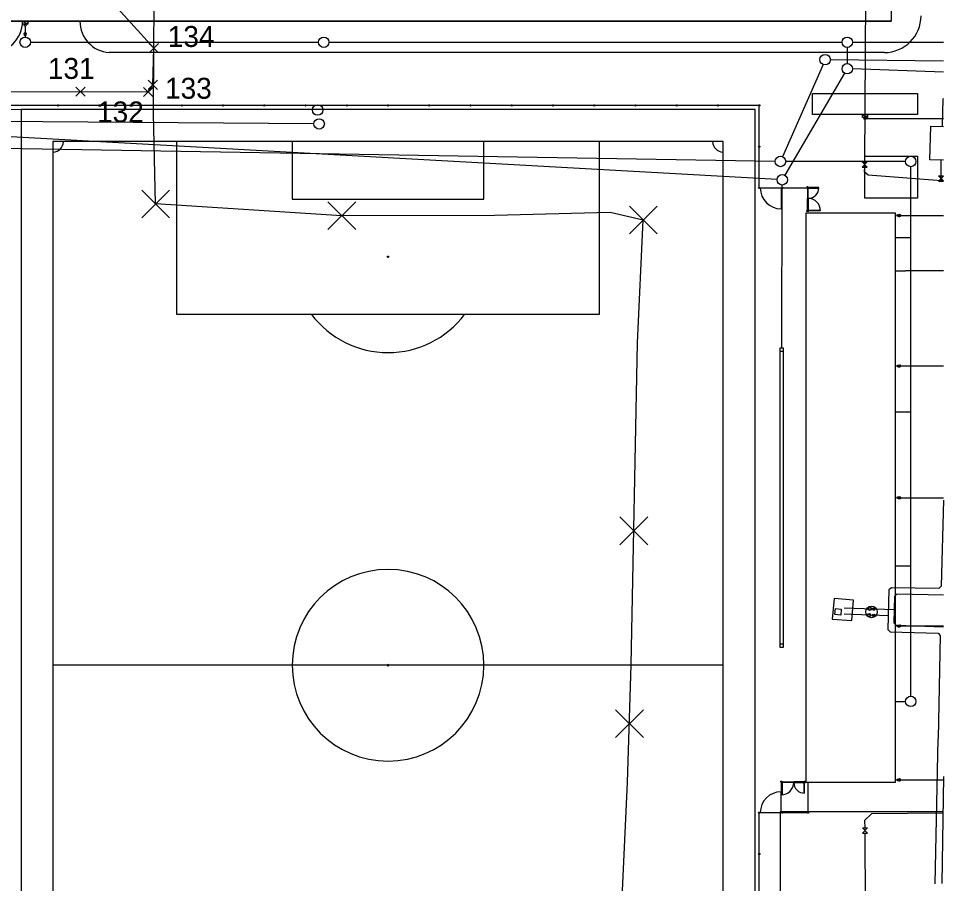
# Model space of a CAD drawing. Extents: x -264205 to -263744, y -1242450 to -1242050.
# Drawn here: x -264042.8 to -263954.5, y -1242261.8 to -1242179.2 of the extents above; entities that cross this region are included whole.
import ezdxf

# ---------------------------------------------------------------- set-up
doc = ezdxf.new("R2010")
doc.units = 0
for name, color, linetype in [('KFA_63-1_TELEKOM_PRELOZKA', 7, 'Continuous'), ('KFA_BODY_CISLO', 7, 'Continuous'), ('KFA_BODY_SYMBOL', 7, 'Continuous'), ('KFA_JESTV_IS_DSP', 7, 'Continuous'), ('KFA_SITUACIA_DSP', 7, 'Continuous'), ('KFA_TELEKOM_POVODNA_TRASA', 7, 'Continuous'), ('POPIS', 7, 'Continuous')]:
    doc.layers.add(name, color=color, linetype=linetype)

msp = doc.modelspace()

# ---------------------------------------------------------------- linework, layer by layer
at = {"layer": 'KFA_63-1_TELEKOM_PRELOZKA'}
msp.add_lwpolyline([(-264119.225, -1242186.724), (-264097.679, -1242186.215), (-264066.654, -1242186.22), (-264036.882, -1242186.217), (-264030.42, -1242186.248), (-264029.972, -1242185.571), (-264029.872, -1242182.075)], dxfattribs=at)
at = {"layer": 'KFA_BODY_SYMBOL'}
for p, q in [((-264030.314, -1242182.517), (-264029.43, -1242181.633)), ((-264029.43, -1242182.517), (-264030.314, -1242181.633)), ((-264029.872, -1242182.075), (-264029.872, -1242182.075)), ((-264037.324, -1242186.659), (-264036.44, -1242185.775)), ((-264036.44, -1242186.659), (-264037.324, -1242185.775)), ((-264030.862, -1242186.69), (-264029.978, -1242185.806)), ((-264029.978, -1242186.69), (-264030.862, -1242185.806)), ((-264030.414, -1242186.013), (-264029.53, -1242185.129)), ((-264029.53, -1242186.013), (-264030.414, -1242185.129)), ((-264029.972, -1242185.571), (-264029.972, -1242185.571)), ((-264036.882, -1242186.217), (-264036.882, -1242186.217)), ((-264030.42, -1242186.248), (-264030.42, -1242186.248))]:
    msp.add_line(p, q, dxfattribs=at)
at = {"layer": 'KFA_JESTV_IS_DSP'}
for p, q in [((-263961.582, -1242115.554), (-263961.999, -1242192.922)), ((-263954.47, -1242183.294), (-263965.273, -1242183.165)), ((-263965.974, -1242183.616), (-263969.841, -1242192.426)), ((-263954.47, -1242184.349), (-263963.161, -1242184.046)), ((-263963.914, -1242184.46), (-263969.615, -1242194.201)), ((-263954.509, -1242186.913), (-263954.47, -1242186.884)), ((-263954.57, -1242189.535), (-263954.509, -1242186.913)), ((-264014.599, -1242189.295), (-264103.868, -1242188.645)), ((-264014.738, -1242187.967), (-264101.789, -1242187.812)), ((-263955.775, -1242192.739), (-263955.679, -1242189.503)), ((-263955.679, -1242189.503), (-263954.47, -1242189.537)), ((-263970.367, -1242194.605), (-264044.102, -1242190.483)), ((-263970.542, -1242192.875), (-264044.328, -1242191.641)), ((-263962.251, -1242192.922), (-263961.751, -1242192.922)), ((-263961.751, -1242192.922), (-263962.251, -1242193.422)), ((-263961.751, -1242193.422), (-263962.251, -1242192.922)), ((-263954.47, -1242192.759), (-263955.775, -1242192.739)), ((-263954.693, -1242194.518), (-263954.696, -1242192.756)), ((-263962.251, -1242193.422), (-263961.751, -1242193.422)), ((-263962.017, -1242193.422), (-263962.046, -1242193.838)), ((-263962.046, -1242193.838), (-263961.65, -1242194.164)), ((-263961.65, -1242194.164), (-263954.663, -1242194.7)), ((-263954.943, -1242194.268), (-263954.47, -1242194.268)), ((-263954.47, -1242194.741), (-263954.943, -1242194.268)), ((-263954.47, -1242194.295), (-263954.943, -1242194.768)), ((-263954.943, -1242194.768), (-263954.47, -1242194.768)), ((-263954.663, -1242194.7), (-263954.693, -1242194.518)), ((-263954.663, -1242194.7), (-263954.47, -1242194.703)), ((-263954.47, -1242225.226), (-263954.692, -1242233.447)), ((-263959.451, -1242233.59), (-263959.696, -1242233.784)), ((-263954.912, -1242233.658), (-263959.451, -1242233.59)), ((-263954.692, -1242233.447), (-263954.912, -1242233.658)), ((-263959.696, -1242233.784), (-263959.771, -1242237.559)), ((-263959.189, -1242236.963), (-263959.11, -1242234.394)), ((-263959.11, -1242234.394), (-263958.895, -1242234.164)), ((-263958.895, -1242234.164), (-263954.47, -1242234.271)), ((-263964.927, -1242234.61), (-263965.088, -1242236.571)), ((-263963.078, -1242234.762), (-263964.927, -1242234.61)), ((-263963.239, -1242236.723), (-263963.078, -1242234.762)), ((-263964.833, -1242236.15), (-263964.786, -1242235.573)), ((-263964.285, -1242236.195), (-263964.833, -1242236.15)), ((-263964.786, -1242235.573), (-263964.238, -1242235.618)), ((-263964.238, -1242235.618), (-263964.285, -1242236.195)), ((-263959.149, -1242235.676), (-263963.972, -1242235.519)), ((-263959.745, -1242236.267), (-263963.952, -1242236.1)), ((-263965.088, -1242236.571), (-263963.239, -1242236.723)), ((-263958.966, -1242237.191), (-263959.189, -1242236.963)), ((-263954.47, -1242237.349), (-263958.966, -1242237.191)), ((-263959.771, -1242237.559), (-263959.557, -1242237.791)), ((-263959.557, -1242237.791), (-263954.983, -1242237.917)), ((-263954.983, -1242237.917), (-263954.788, -1242238.153)), ((-263954.788, -1242238.153), (-263954.978, -1242247.991)), ((-263955.264, -1242261.849), (-263954.978, -1242247.991)), ((-263954.47, -1242251.609), (-263954.644, -1242261.82)), ((-263961.355, -1242255.168), (-263962.028, -1242255.805)), ((-263954.47, -1242255.107), (-263961.355, -1242255.168)), ((-263962.221, -1242256.501), (-263961.721, -1242256.501)), ((-263961.721, -1242256.501), (-263962.221, -1242257.001)), ((-263961.721, -1242257.001), (-263962.221, -1242256.501)), ((-263962.028, -1242255.805), (-263961.971, -1242256.501)), ((-263962.221, -1242257.001), (-263961.721, -1242257.001)), ((-263961.971, -1242257.001), (-263961.846, -1242321.299))]:
    msp.add_line(p, q, dxfattribs=at)
for centre, radius in [((-263965.773, -1242183.159), 0.5), ((-263963.661, -1242184.028), 0.5), ((-264014.238, -1242187.968), 0.5), ((-264014.099, -1242189.299), 0.5), ((-263970.042, -1242192.883), 0.5), ((-263969.868, -1242194.633), 0.5), ((-263961.345, -1242235.895), 0.556), ((-263961.522, -1242235.583), 0.164), ((-263961.583, -1242236.191), 0.164), ((-263961.138, -1242235.62), 0.122), ((-263961.128, -1242236.214), 0.122)]:
    msp.add_circle(centre, radius, dxfattribs=at)
at = {"layer": 'KFA_SITUACIA_DSP'}
for p, q in [((-263959.468, -1242059.534), (-263959.468, -1242179.482)), ((-264131.568, -1242179.482), (-263959.468, -1242179.482)), ((-263959.468, -1242179.482), (-264131.568, -1242179.482)), ((-263959.468, -1242179.482), (-264077.23, -1242179.482)), ((-264042.417, -1242179.482), (-264041.917, -1242179.482)), ((-264042.417, -1242179.772), (-264042.417, -1242179.482)), ((-264042.417, -1242179.482), (-264041.917, -1242179.772)), ((-264042.417, -1242179.482), (-264041.917, -1242179.772)), ((-264041.917, -1242179.482), (-264042.417, -1242179.482)), ((-264041.917, -1242179.772), (-264042.417, -1242179.772)), ((-264041.917, -1242179.482), (-264041.917, -1242179.772)), ((-264041.917, -1242179.772), (-264041.917, -1242179.482)), ((-264042.167, -1242179.972), (-264042.167, -1242181)), ((-264041.667, -1242181.5), (-264014.161, -1242181.5)), ((-264013.161, -1242181.5), (-263964.161, -1242181.5)), ((-263963.161, -1242181.5), (-263954.47, -1242181.5)), ((-263963.661, -1242182), (-263963.661, -1242183.528)), ((-263960.118, -1242182.482), (-264034.158, -1242182.482)), ((-263972.068, -1242187.532), (-264118.068, -1242187.532)), ((-264039.089, -1242187.532), (-264038.969, -1242187.532)), ((-264039.029, -1242187.592), (-264039.029, -1242187.472)), ((-264035.15, -1242187.532), (-264035.03, -1242187.532)), ((-264035.09, -1242187.592), (-264035.09, -1242187.472)), ((-264031.211, -1242187.532), (-264031.091, -1242187.532)), ((-264031.151, -1242187.592), (-264031.151, -1242187.472)), ((-264027.272, -1242187.532), (-264027.152, -1242187.532)), ((-264027.212, -1242187.592), (-264027.212, -1242187.472)), ((-264023.333, -1242187.532), (-264023.213, -1242187.532)), ((-264023.273, -1242187.592), (-264023.273, -1242187.472)), ((-264019.394, -1242187.532), (-264019.274, -1242187.532)), ((-264019.334, -1242187.592), (-264019.334, -1242187.472)), ((-264015.456, -1242187.532), (-264015.336, -1242187.532)), ((-264015.396, -1242187.592), (-264015.396, -1242187.472)), ((-264011.517, -1242187.532), (-264011.397, -1242187.532)), ((-264011.457, -1242187.592), (-264011.457, -1242187.472)), ((-264007.578, -1242187.532), (-264007.458, -1242187.532)), ((-264007.518, -1242187.592), (-264007.518, -1242187.472)), ((-264003.639, -1242187.532), (-264003.519, -1242187.532)), ((-264003.579, -1242187.592), (-264003.579, -1242187.472)), ((-263999.7, -1242187.532), (-263999.58, -1242187.532)), ((-263999.64, -1242187.592), (-263999.64, -1242187.472)), ((-263995.761, -1242187.532), (-263995.641, -1242187.532)), ((-263995.701, -1242187.592), (-263995.701, -1242187.472)), ((-263991.822, -1242187.532), (-263991.702, -1242187.532)), ((-263991.762, -1242187.592), (-263991.762, -1242187.472)), ((-263987.883, -1242187.532), (-263987.763, -1242187.532)), ((-263987.823, -1242187.592), (-263987.823, -1242187.472)), ((-263983.944, -1242187.532), (-263983.824, -1242187.532)), ((-263983.884, -1242187.592), (-263983.884, -1242187.472)), ((-263980.006, -1242187.532), (-263979.886, -1242187.532)), ((-263979.946, -1242187.592), (-263979.946, -1242187.472)), ((-263976.067, -1242187.532), (-263975.947, -1242187.532)), ((-263976.007, -1242187.592), (-263976.007, -1242187.472)), ((-263972.128, -1242187.532), (-263972.008, -1242187.532)), ((-263972.068, -1242187.592), (-263972.068, -1242187.472)), ((-263972.068, -1242195.407), (-263972.068, -1242187.532)), ((-263962.218, -1242188.382), (-263961.718, -1242188.382)), ((-263962.218, -1242188.672), (-263962.218, -1242188.382)), ((-263962.218, -1242188.382), (-263961.718, -1242188.672)), ((-263962.218, -1242188.382), (-263961.718, -1242188.672)), ((-263961.718, -1242188.382), (-263962.218, -1242188.382)), ((-263961.718, -1242188.382), (-263961.718, -1242188.672)), ((-263961.718, -1242188.672), (-263961.718, -1242188.382)), ((-263961.718, -1242188.672), (-263962.218, -1242188.672)), ((-263961.868, -1242188.772), (-263954.47, -1242188.772)), ((-263975.518, -1242190.982), (-264039.518, -1242190.982)), ((-264039.518, -1242190.982), (-264039.518, -1242290.982)), ((-264027.678, -1242207.482), (-264027.678, -1242190.982)), ((-264016.678, -1242190.982), (-264016.678, -1242196.482)), ((-263998.358, -1242196.482), (-263998.358, -1242190.982)), ((-263987.358, -1242190.982), (-263987.358, -1242207.482)), ((-263975.518, -1242290.982), (-263975.518, -1242190.982)), ((-263972.128, -1242191.47), (-263972.008, -1242191.47)), ((-263972.068, -1242191.41), (-263972.068, -1242191.53)), ((-263958.097, -1242192.883), (-263969.542, -1242192.883)), ((-263957.597, -1242243.932), (-263957.597, -1242193.383)), ((-263972.068, -1242195.407), (-263967.418, -1242195.407)), ((-263969.968, -1242195.407), (-263969.968, -1242197.407)), ((-263969.921, -1242210.683), (-263969.869, -1242195.133)), ((-263967.413, -1242195.307), (-263967.513, -1242195.307)), ((-263967.513, -1242195.307), (-263967.513, -1242195.407)), ((-263967.513, -1242195.407), (-263967.413, -1242195.407)), ((-263967.425, -1242195.32), (-263967.5, -1242195.32)), ((-263967.5, -1242195.32), (-263967.5, -1242195.395)), ((-263967.5, -1242195.395), (-263967.425, -1242195.395)), ((-263967.463, -1242195.407), (-263967.463, -1242196.395)), ((-263967.388, -1242195.407), (-263967.463, -1242195.407)), ((-263967.425, -1242195.395), (-263967.425, -1242195.32)), ((-263967.425, -1242195.395), (-263967.425, -1242195.345)), ((-263967.425, -1242195.345), (-263967.325, -1242195.345)), ((-263967.413, -1242195.407), (-263967.413, -1242195.307)), ((-263967.413, -1242195.357), (-263967.363, -1242195.357)), ((-263967.388, -1242196.395), (-263967.388, -1242195.407)), ((-263967.363, -1242195.457), (-263967.388, -1242195.457)), ((-263966.388, -1242195.371), (-263967.375, -1242195.37)), ((-263967.375, -1242195.37), (-263967.375, -1242195.445)), ((-263967.375, -1242195.445), (-263966.388, -1242195.446)), ((-263967.363, -1242195.357), (-263967.363, -1242195.457)), ((-263967.325, -1242195.345), (-263967.325, -1242195.37)), ((-264016.678, -1242196.482), (-263998.358, -1242196.482)), ((-263967.463, -1242197.557), (-263967.463, -1242196.42)), ((-263967.388, -1242196.42), (-263967.388, -1242197.557)), ((-263967.593, -1242252.182), (-263967.593, -1242197.782)), ((-263967.593, -1242197.782), (-263959.093, -1242197.782)), ((-263967.593, -1242197.782), (-263959.097, -1242197.782)), ((-263967.593, -1242252.182), (-263967.593, -1242197.782)), ((-263967.513, -1242197.557), (-263967.413, -1242197.557)), ((-263967.513, -1242197.657), (-263967.513, -1242197.557)), ((-263967.413, -1242197.657), (-263967.513, -1242197.657)), ((-263967.5, -1242197.57), (-263967.425, -1242197.57)), ((-263967.5, -1242197.645), (-263967.5, -1242197.57)), ((-263967.425, -1242197.645), (-263967.5, -1242197.645)), ((-263967.478, -1242197.782), (-263967.358, -1242197.782)), ((-263967.388, -1242197.557), (-263967.463, -1242197.557)), ((-263967.425, -1242197.57), (-263967.425, -1242197.62)), ((-263967.425, -1242197.57), (-263967.425, -1242197.645)), ((-263967.425, -1242197.62), (-263967.325, -1242197.62)), ((-263967.413, -1242197.557), (-263967.413, -1242197.657)), ((-263967.413, -1242197.607), (-263967.363, -1242197.607)), ((-263967.363, -1242197.507), (-263967.388, -1242197.507)), ((-263967.375, -1242197.52), (-263966.238, -1242197.52)), ((-263967.375, -1242197.595), (-263967.375, -1242197.52)), ((-263966.238, -1242197.595), (-263967.375, -1242197.595)), ((-263967.363, -1242197.607), (-263967.363, -1242197.507)), ((-263967.325, -1242197.62), (-263967.325, -1242197.595)), ((-263959.097, -1242197.782), (-263959.093, -1242252.182)), ((-263959.093, -1242197.782), (-263959.093, -1242252.182)), ((-263958.799, -1242197.962), (-263958.762, -1242197.962)), ((-263958.799, -1242198.102), (-263958.762, -1242198.102)), ((-263958.762, -1242197.962), (-263958.742, -1242197.942)), ((-263958.762, -1242198.102), (-263958.742, -1242198.122)), ((-263958.742, -1242197.942), (-263958.637, -1242197.942)), ((-263958.742, -1242198.122), (-263958.637, -1242198.122)), ((-263958.575, -1242198.032), (-263954.47, -1242198.032)), ((-263959.097, -1242200.132), (-263957.597, -1242200.132)), ((-263959.097, -1242203.332), (-263958.097, -1242203.332)), ((-263954.47, -1242203.332), (-263958.097, -1242203.332)), ((-263987.358, -1242207.482), (-264027.678, -1242207.482)), ((-263970.071, -1242210.684), (-263969.77, -1242210.682)), ((-263970.07, -1242239.282), (-263970.071, -1242210.684)), ((-263969.77, -1242210.682), (-263969.77, -1242239.282)), ((-263970.071, -1242210.983), (-263969.771, -1242210.985)), ((-263958.799, -1242212.337), (-263958.762, -1242212.337)), ((-263958.799, -1242212.477), (-263958.762, -1242212.477)), ((-263958.762, -1242212.337), (-263958.742, -1242212.317)), ((-263958.762, -1242212.477), (-263958.742, -1242212.497)), ((-263958.742, -1242212.317), (-263958.637, -1242212.317)), ((-263958.742, -1242212.497), (-263958.637, -1242212.497)), ((-263958.575, -1242212.407), (-263954.47, -1242212.407)), ((-263959.097, -1242216.782), (-263957.597, -1242216.782)), ((-263958.799, -1242224.912), (-263958.762, -1242224.912)), ((-263958.799, -1242225.052), (-263958.762, -1242225.052)), ((-263958.762, -1242224.912), (-263958.742, -1242224.892)), ((-263958.762, -1242225.052), (-263958.742, -1242225.072)), ((-263958.742, -1242224.892), (-263958.637, -1242224.892)), ((-263958.742, -1242225.072), (-263958.637, -1242225.072)), ((-263958.575, -1242224.982), (-263954.47, -1242224.982)), ((-263959.097, -1242231.482), (-263957.597, -1242231.482)), ((-263958.799, -1242237.162), (-263958.762, -1242237.162)), ((-263958.762, -1242237.162), (-263958.742, -1242237.142)), ((-263958.742, -1242237.142), (-263958.637, -1242237.142)), ((-263958.575, -1242237.232), (-263954.47, -1242237.232)), ((-263958.799, -1242237.302), (-263958.762, -1242237.302)), ((-263958.762, -1242237.302), (-263958.742, -1242237.322)), ((-263958.742, -1242237.322), (-263958.637, -1242237.322)), ((-263969.77, -1242238.982), (-263970.07, -1242238.982)), ((-263969.77, -1242239.282), (-263970.07, -1242239.282)), ((-263975.518, -1242240.982), (-264039.518, -1242240.982)), ((-263959.097, -1242244.432), (-263958.097, -1242244.432)), ((-263970.018, -1242252.152), (-263970.018, -1242252.052)), ((-263970.018, -1242252.052), (-263969.918, -1242252.052)), ((-263969.918, -1242252.152), (-263970.018, -1242252.152)), ((-263970.005, -1242252.14), (-263970.005, -1242252.065)), ((-263970.005, -1242252.065), (-263969.93, -1242252.065)), ((-263969.93, -1242252.14), (-263970.005, -1242252.14)), ((-263969.93, -1242252.14), (-263969.98, -1242252.14)), ((-263969.98, -1242252.14), (-263969.98, -1242252.24)), ((-263969.98, -1242252.24), (-263969.955, -1242252.24)), ((-263969.968, -1242252.152), (-263969.968, -1242252.202)), ((-263969.968, -1242252.202), (-263969.868, -1242252.202)), ((-263969.955, -1242253.327), (-263969.955, -1242252.19)), ((-263969.955, -1242252.19), (-263969.88, -1242252.19)), ((-263969.93, -1242252.065), (-263969.93, -1242252.14)), ((-263969.918, -1242252.052), (-263969.918, -1242252.152)), ((-263969.918, -1242252.102), (-263968.78, -1242252.102)), ((-263969.918, -1242252.177), (-263969.918, -1242252.102)), ((-263968.78, -1242252.177), (-263969.918, -1242252.177)), ((-263969.88, -1242252.19), (-263969.88, -1242253.327)), ((-263969.868, -1242252.202), (-263969.868, -1242252.177)), ((-263968.78, -1242252.102), (-263968.78, -1242252.177)), ((-263967.768, -1242252.102), (-263968.755, -1242252.102)), ((-263968.755, -1242252.102), (-263968.755, -1242252.177)), ((-263968.755, -1242252.177), (-263967.768, -1242252.177)), ((-263967.818, -1242252.202), (-263967.818, -1242252.177)), ((-263967.718, -1242252.202), (-263967.818, -1242252.202)), ((-263967.805, -1242252.19), (-263967.807, -1242253.177)), ((-263967.73, -1242252.19), (-263967.805, -1242252.19)), ((-263967.768, -1242252.152), (-263967.768, -1242252.052)), ((-263967.768, -1242252.052), (-263967.668, -1242252.052)), ((-263967.768, -1242252.177), (-263967.768, -1242252.102)), ((-263967.668, -1242252.152), (-263967.768, -1242252.152)), ((-263967.755, -1242252.14), (-263967.755, -1242252.065)), ((-263967.755, -1242252.065), (-263967.68, -1242252.065)), ((-263967.755, -1242252.14), (-263967.705, -1242252.14)), ((-263967.68, -1242252.14), (-263967.755, -1242252.14)), ((-263967.732, -1242253.177), (-263967.73, -1242252.19)), ((-263967.705, -1242252.24), (-263967.73, -1242252.24)), ((-263967.718, -1242252.152), (-263967.718, -1242252.202)), ((-263967.705, -1242252.14), (-263967.705, -1242252.24)), ((-263967.68, -1242252.065), (-263967.68, -1242252.14)), ((-263967.668, -1242252.052), (-263967.668, -1242252.152)), ((-263959.093, -1242252.182), (-263967.593, -1242252.182)), ((-263959.093, -1242252.182), (-263967.593, -1242252.182)), ((-263967.418, -1242252.182), (-263967.418, -1242255.057)), ((-263958.799, -1242251.862), (-263958.762, -1242251.862)), ((-263958.799, -1242252.002), (-263958.762, -1242252.002)), ((-263958.762, -1242251.862), (-263958.742, -1242251.842)), ((-263958.762, -1242252.002), (-263958.742, -1242252.022)), ((-263958.742, -1242251.842), (-263958.637, -1242251.842)), ((-263958.742, -1242252.022), (-263958.637, -1242252.022)), ((-263958.575, -1242251.932), (-263954.47, -1242251.932)), ((-263969.968, -1242255.057), (-263969.968, -1242253.057)), ((-263972.128, -1242255.057), (-263972.008, -1242255.057)), ((-263972.068, -1242255.117), (-263972.068, -1242254.997)), ((-263972.068, -1242255.057), (-263967.418, -1242255.057)), ((-263972.068, -1242294.432), (-263972.068, -1242255.057)), ((-263969.928, -1242255.057), (-263969.808, -1242255.057)), ((-263969.868, -1242255.117), (-263969.868, -1242254.997)), ((-263967.478, -1242255.057), (-263967.358, -1242255.057)), ((-263967.418, -1242255.117), (-263967.418, -1242254.997)), ((-263972.128, -1242258.995), (-263972.008, -1242258.995)), ((-263972.068, -1242259.055), (-263972.068, -1242258.935))]:
    msp.add_line(p, q, dxfattribs=at)
for points in [[(-263966.968, -1242186.382), (-263956.968, -1242186.382), (-263956.968, -1242188.382), (-263966.968, -1242188.382)], [(-264042.568, -1242294.032), (-263972.468, -1242294.032), (-263972.468, -1242187.932), (-264042.568, -1242187.932)], [(-263961.968, -1242192.382), (-263956.968, -1242192.382), (-263956.968, -1242196.382), (-263961.968, -1242196.382)], [(-263967.597, -1242197.782), (-263959.097, -1242197.782), (-263959.097, -1242252.182), (-263967.597, -1242252.182)]]:
    msp.add_lwpolyline(points, close=True, dxfattribs=at)
msp.add_lwpolyline([(-263954.47, -1242254.982), (-263970.077, -1242254.982), (-263970.077, -1242263.982), (-263954.47, -1242263.982)], dxfattribs=at)
for centre, radius in [((-264042.167, -1242179.872), 0.1), ((-264042.167, -1242181.5), 0.5), ((-264013.661, -1242181.5), 0.5), ((-263963.661, -1242181.5), 0.5), ((-264039.029, -1242187.532), 0.06), ((-264035.09, -1242187.532), 0.06), ((-264031.151, -1242187.532), 0.06), ((-264027.212, -1242187.532), 0.06), ((-264023.273, -1242187.532), 0.06), ((-264019.334, -1242187.532), 0.06), ((-264015.396, -1242187.532), 0.06), ((-264011.457, -1242187.532), 0.06), ((-264007.518, -1242187.532), 0.06), ((-264003.579, -1242187.532), 0.06), ((-263999.64, -1242187.532), 0.06), ((-263995.701, -1242187.532), 0.06), ((-263991.762, -1242187.532), 0.06), ((-263987.823, -1242187.532), 0.06), ((-263983.884, -1242187.532), 0.06), ((-263979.946, -1242187.532), 0.06), ((-263976.007, -1242187.532), 0.06), ((-263972.068, -1242187.532), 0.06), ((-263961.968, -1242188.772), 0.1), ((-263972.068, -1242191.47), 0.06), ((-263957.597, -1242192.883), 0.5), ((-263969.868, -1242194.633), 0.5), ((-263972.068, -1242195.407), 0.06), ((-263969.868, -1242195.407), 0.06), ((-263958.847, -1242198.032), 0.085), ((-263958.847, -1242198.032), 0.0625), ((-263958.637, -1242198.032), 0.0625), ((-264007.518, -1242201.982), 0.06), ((-263958.847, -1242212.407), 0.085), ((-263958.847, -1242212.407), 0.0625), ((-263958.637, -1242212.407), 0.0625), ((-263958.847, -1242224.982), 0.085), ((-263958.847, -1242224.982), 0.0625), ((-263958.637, -1242224.982), 0.0625), ((-263958.847, -1242237.232), 0.085), ((-263958.847, -1242237.232), 0.0625), ((-263958.637, -1242237.232), 0.0625), ((-263957.597, -1242244.432), 0.5), ((-263958.847, -1242251.932), 0.085), ((-263958.847, -1242251.932), 0.0625), ((-263958.637, -1242251.932), 0.0625), ((-263972.068, -1242255.057), 0.06), ((-263969.868, -1242255.057), 0.06), ((-263967.418, -1242255.057), 0.06), ((-263972.068, -1242258.995), 0.06)]:
    msp.add_circle(centre, radius, dxfattribs=at)
for centre, radius, start, end in [((-264045.412, -1242179.495), 2.994, 266.03136, 0.25001), ((-264033.951, -1242179.495), 2.994, 179.74999, 266.03136), ((-263960.118, -1242178.982), 3.5, 270, 0), ((-264042.167, -1242180.736), 0.125, 0, 180), ((-264042.167, -1242180.736), 0.125, 180, 0), ((-264039.518, -1242190.982), 1, 270, 360), ((-263975.518, -1242190.982), 1, 180, 270), ((-263969.968, -1242195.407), 2, 180, 270), ((-263967.4, -1242195.382), 1.025, 270.60954, 0.60953), ((-263967.4, -1242197.582), 1.175, 359.39047, 89.39046), ((-263958.637, -1242198.032), 0.09, 270, 90), ((-264007.518, -1242201.982), 0.0303, 90, 270), ((-264007.518, -1242201.982), 0.0303, 270, 90), ((-264007.518, -1242201.982), 9.15, 216.94821, 323.05179), ((-263958.637, -1242212.407), 0.09, 270, 90), ((-263958.637, -1242224.982), 0.09, 270, 90), ((-264007.518, -1242240.982), 9.15, 360, 180), ((-263958.637, -1242237.232), 0.09, 270, 90), ((-264007.518, -1242240.982), 9.15, 180, 360), ((-264007.518, -1242240.982), 0.0605, 90, 270), ((-264007.518, -1242240.982), 0.0605, 270, 90), ((-263969.943, -1242252.165), 1.175, 269.39046, 359.39047), ((-263967.743, -1242252.165), 1.025, 180.60953, 270.60954), ((-263958.637, -1242251.932), 0.09, 270, 90), ((-263969.968, -1242255.057), 2, 90, 180)]:
    msp.add_arc(centre, radius, start, end, dxfattribs=at)
for centre in [(-263967.4, -1242195.382), (-263967.4, -1242195.382), (-263967.4, -1242197.582), (-263969.943, -1242252.165), (-263969.943, -1242252.165), (-263967.743, -1242252.165)]:
    msp.add_ellipse(centre, major_axis=(0, 0.0125), ratio=0.999995, dxfattribs=at)
at = {"layer": 'KFA_TELEKOM_POVODNA_TRASA'}
for p, q in [((-264029.913, -1242188.318), (-264029.589, -1242139.822)), ((-264029.719, -1242196.934), (-264029.913, -1242188.318)), ((-264031.045, -1242198.26), (-264028.393, -1242195.608)), ((-264028.393, -1242198.26), (-264031.045, -1242195.608)), ((-264011.931, -1242198.062), (-264029.719, -1242196.934)), ((-264013.257, -1242199.388), (-264010.605, -1242196.736)), ((-264010.605, -1242199.388), (-264013.257, -1242196.736)), ((-263984.466, -1242199.8), (-263981.814, -1242197.148)), ((-263981.814, -1242199.8), (-263984.466, -1242197.148)), ((-263997.36, -1242198.031), (-264011.931, -1242198.062)), ((-263986.295, -1242197.77), (-263997.36, -1242198.031)), ((-263983.14, -1242198.474), (-263986.295, -1242197.77)), ((-263983.691, -1242210.183), (-263983.14, -1242198.474)), ((-263984.287, -1242240.935), (-263983.691, -1242210.183)), ((-263985.365, -1242229.475), (-263982.713, -1242226.823)), ((-263982.713, -1242229.475), (-263985.365, -1242226.823)), ((-263984.635, -1242252.165), (-263984.287, -1242240.935)), ((-263985.787, -1242247.876), (-263983.135, -1242245.224)), ((-263983.135, -1242247.876), (-263985.787, -1242245.224)), ((-263985.267, -1242265.602), (-263984.635, -1242252.165))]:
    msp.add_line(p, q, dxfattribs=at)
at = {"layer": 'POPIS'}
msp.add_line((-264029.872, -1242182.075), (-264042.71, -1242167.902), dxfattribs=at)

# ---------------------------------------------------------------- texts
at = {"layer": 'KFA_BODY_CISLO'}
for s, p in [('134', (-264028.554, -1242181.948)), ('131', (-264040.001, -1242184.998)), ('133', (-264028.814, -1242186.893)), ('132', (-264035.307, -1242189.153))]:
    msp.add_text(s, height=2, dxfattribs=at).set_placement(p)

doc.saveas('drawing.dxf')
